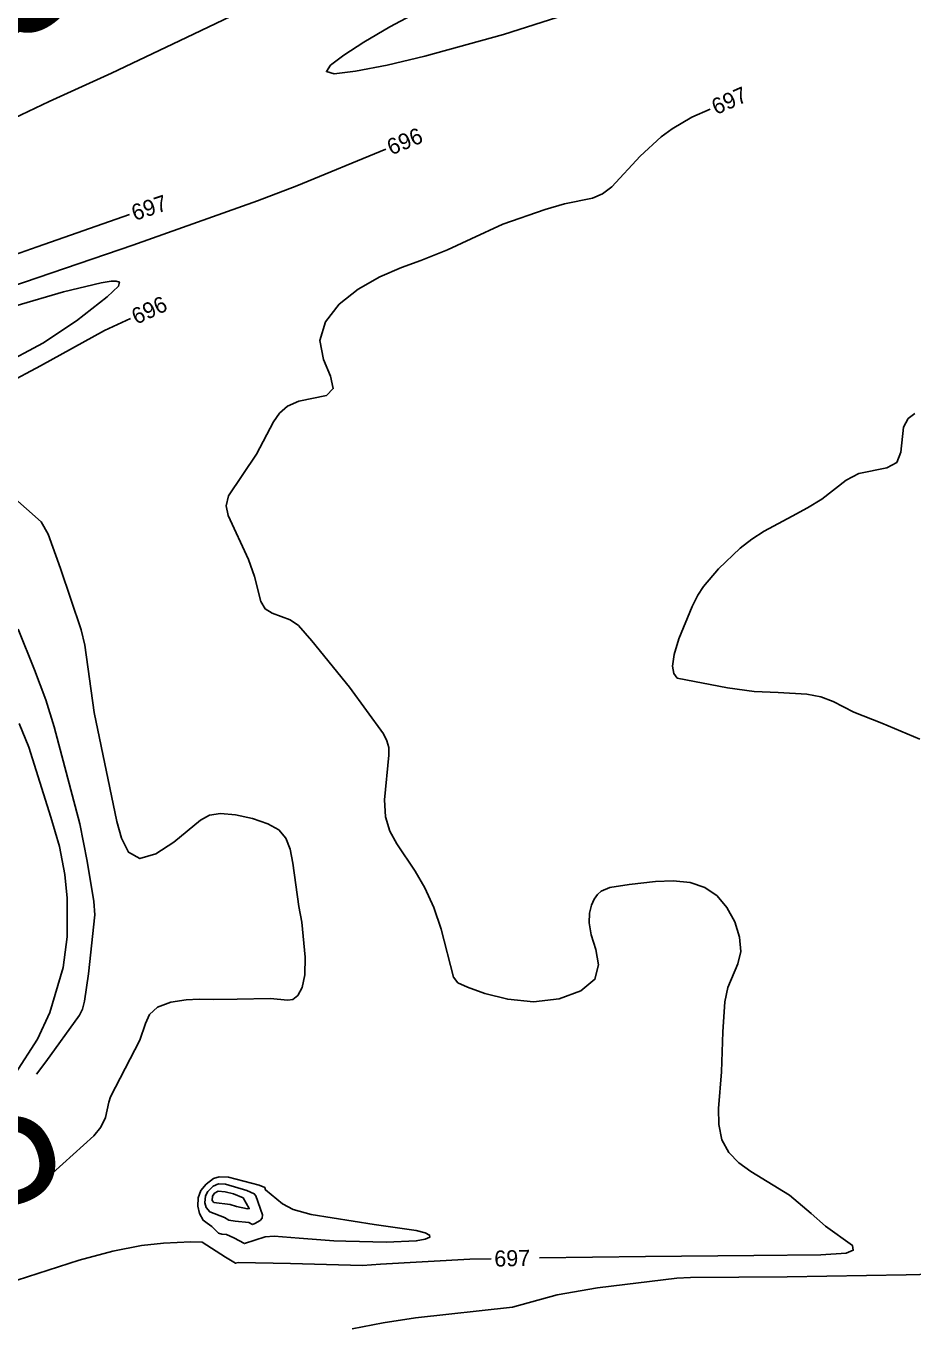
# Model space of a CAD drawing. Extents: x -291892836 to 2945206, y -477993085 to 1832792.
# Drawn here: x 1851693.8 to 1851914.3, y 543914.3 to 544238.1 of the extents above; entities that cross this region are included whole.
import ezdxf

# ---------------------------------------------------------------- set-up
doc = ezdxf.new("R2010")
doc.units = 0
for name, color, linetype in [('DT_X_Contour_Minor', 7, 'Continuous'), ('DT_X_Terrain_Ground_Line', 7, 'Continuous'), ('Level 19', 7, 'Continuous')]:
    doc.layers.add(name, color=color, linetype=linetype)

msp = doc.modelspace()

# ---------------------------------------------------------------- linework, layer by layer
at = {"layer": 'DT_X_Contour_Minor'}
for points in [[(1851931.69, 544281.76), (1851910.49, 544273.12), (1851880.59, 544261.04), (1851851.63, 544249.92), (1851827.79, 544240.92), (1851812.52, 544236.04), (1851792.96, 544230.62), (1851783.55, 544228.39), (1851775.68, 544226.85), (1851770.39, 544226.25), (1851768.46, 544226.78), (1851769.49, 544228.37), (1851772.8, 544230.86), (1851777.79, 544234.1), (1851784.27, 544237.92), (1851792.16, 544242.16), (1851820.5, 544255.9), (1851837.67, 544264.91), (1851860.88, 544277.83), (1851881.54, 544289.37), (1851910.29, 544305.1), (1851930.59, 544315.55)], [(1851761.6, 544248.69), (1851735.43, 544236.06), (1851715.03, 544226.43), (1851699.52, 544219.38), (1851687.28, 544213.58), (1851657.96, 544200.39), (1851642.9, 544193.34), (1851622.56, 544183.28), (1851599.45, 544170.67), (1851574.61, 544158.3), (1851546, 544145.08), (1851535.48, 544140.27), (1851545.35, 544141.39), (1851563.49, 544143.64), (1851572.51, 544144.56), (1851577.67, 544145.61), (1851591.83, 544149.73), (1851603.5, 544153.32), (1851607.02, 544154.06), (1851619.76, 544157.73), (1851652.44, 544167.79), (1851666.89, 544172.72), (1851696.51, 544183.18), (1851719.47, 544191.24)], [(1851701.81, 544242.92), (1851692.99, 544237.39), (1851689.94, 544235.33), (1851685.86, 544232.88), (1851672.96, 544226.1), (1851648.68, 544213.9), (1851621.28, 544200.35), (1851614.41, 544197.2), (1851607.53, 544194.36), (1851583.78, 544185.51), (1851556.7, 544174.12), (1851530.45, 544164.25), (1851502.49, 544153.19), (1851472.56, 544141.47), (1851436.91, 544127.59), (1851413.91, 544119.01), (1851376.2, 544105.75), (1851343.56, 544094.54), (1851329.79, 544091.13), (1851296.36, 544083.01), (1851285.66, 544080.19), (1851270.99, 544072.75)], [(1851863.88, 544217.47), (1851859.34, 544215.46), (1851854.46, 544212.53), (1851851.73, 544210.55), (1851846.46, 544205.74), (1851839.44, 544198.12), (1851837.12, 544196.35), (1851834.6, 544195.33), (1851827.7, 544193.86), (1851822.82, 544192.51), (1851812.36, 544188.79), (1851804.43, 544185.21), (1851798.6, 544182.45), (1851791.92, 544179.82), (1851787.15, 544178.03), (1851781.75, 544175.69), (1851776.36, 544172.67), (1851771.62, 544168.9), (1851768.22, 544164.55), (1851766.84, 544159.89), (1851767.75, 544155.2), (1851769.49, 544151.02), (1851770.18, 544147.92), (1851768.47, 544146.25), (1851761.57, 544144.76), (1851758.77, 544143.54), (1851756.76, 544141.8), (1851755.3, 544139.7), (1851751.08, 544131.62), (1851744.11, 544121.28), (1851743.51, 544118.74), (1851744.06, 544116.38), (1851749.11, 544105.38), (1851750.61, 544101.18), (1851752.18, 544094.98), (1851753.19, 544093.13), (1851754.94, 544092.06), (1851759.46, 544090.44), (1851761.48, 544088.99), (1851764.84, 544085.19), (1851774.22, 544073.62), (1851782.62, 544062.01), (1851783.52, 544060.29), (1851783.94, 544058.68), (1851783.96, 544056.75), (1851782.94, 544045.67), (1851783.18, 544041.38), (1851784.21, 544037.8), (1851785.93, 544034.67), (1851790.53, 544027.91), (1851792.97, 544023.72), (1851795.19, 544018.87), (1851797.02, 544013.44), (1851800.06, 544001.51), (1851801.18, 544000.14), (1851803.58, 543999.01), (1851807.86, 543997.49), (1851813.57, 543996.04), (1851819.99, 543995.4), (1851826.36, 543996.12), (1851831.75, 543998.09), (1851835.22, 544001.02), (1851836.15, 544004.61), (1851835.43, 544008.43), (1851834.3, 544012.02), (1851833.78, 544015.03), (1851833.87, 544017.46), (1851834.35, 544019.39), (1851835.03, 544020.92), (1851835.85, 544022.08), (1851836.78, 544022.91), (1851838.96, 544023.82), (1851843.71, 544024.58), (1851850.33, 544025.3), (1851854.68, 544025.45), (1851858.93, 544025.04), (1851862.59, 544023.81), (1851865.61, 544021.73), (1851868.06, 544018.86), (1851869.98, 544015.3), (1851871.2, 544011.47), (1851871.49, 544007.87), (1851870.78, 544004.81), (1851868.26, 543998.95), (1851867.49, 543995.36), (1851867.02, 543987.94), (1851866.73, 543977.93), (1851865.93, 543968.87), (1851866.02, 543964.88), (1851866.81, 543961.09), (1851868.52, 543957.93), (1851871, 543955.33), (1851873.98, 543953.14), (1851883.64, 543947.26), (1851888.97, 543942.77), (1851892.59, 543939.57), (1851899.26, 543934.77), (1851899.48, 543933.59), (1851897.68, 543932.89), (1851891.39, 543932.45), (1851874.73, 543932.3)], [(1851689.97, 544173.25), (1851720.33, 544183.6), (1851751.34, 544194.65), (1851761.1, 544198.39), (1851783.21, 544207.51)], [(1851687.43, 544153.59), (1851697.91, 544159.21), (1851706.3, 544164.81), (1851713.97, 544170.72), (1851716.73, 544173.43), (1851717.03, 544174.39), (1851716.19, 544174.67), (1851714.97, 544174.64), (1851712.49, 544174.25), (1851703.06, 544171.99), (1851691.27, 544168.51)], [(1851719.77, 544165.33), (1851713.3, 544162.35), (1851697.37, 544153.57), (1851689.03, 544149.1)], [(1851916.04, 544060.73), (1851906.57, 544064.7), (1851899.58, 544067.42), (1851894.51, 544070.09), (1851891.4, 544071.24), (1851887.89, 544071.91), (1851880.78, 544072.32), (1851874.84, 544072.6), (1851868.19, 544073.52), (1851855.68, 544075.92), (1851854.83, 544077.04), (1851854.51, 544078.92), (1851854.91, 544081.78), (1851856.1, 544085.66), (1851859.42, 544093.75), (1851860.84, 544096.55), (1851862.2, 544098.68), (1851865.98, 544103.1), (1851871.34, 544108.21), (1851874.22, 544110.44), (1851877.28, 544112.44), (1851884.31, 544116.23), (1851888.09, 544118.24), (1851891.64, 544120.45), (1851897.72, 544125.13), (1851900.88, 544126.79), (1851907.83, 544128.22), (1851910.28, 544129.52), (1851911.33, 544132.09), (1851911.95, 544138.34), (1851913.09, 544140.45), (1851914.75, 544141.71)], [(1851690.21, 544121.26), (1851697.54, 544114.76), (1851699.27, 544111.72), (1851702.31, 544103.21), (1851707.5, 544087.95), (1851708.39, 544084.12), (1851710.72, 544067.34), (1851716.38, 544040.26), (1851717.49, 544036.11), (1851719.28, 544032.6), (1851722.09, 544031.01), (1851726.08, 544032.16), (1851730.51, 544035.06), (1851737.18, 544040.54), (1851739.42, 544041.8), (1851742.09, 544042.19), (1851745.84, 544041.86), (1851750.08, 544040.97), (1851753.92, 544039.69), (1851756.65, 544038.14), (1851758.4, 544036.13), (1851759.47, 544033.4), (1851760.15, 544029.86), (1851761.59, 544019.11), (1851762.35, 544015.21), (1851763.19, 544006.46), (1851763.12, 544002.1), (1851762.46, 543998.94), (1851761.38, 543996.97), (1851760.14, 543995.99), (1851758.85, 543995.77), (1851754.45, 543996.18), (1851746.26, 543996.03), (1851740.44, 543995.94), (1851736.84, 543996.06), (1851733.58, 543995.86), (1851729.77, 543995.26), (1851726.49, 543994.07), (1851724.49, 543992.2), (1851723.47, 543989.96), (1851722.07, 543985.85), (1851714.76, 543971.79), (1851714.35, 543970.43), (1851713.53, 543966.64), (1851712.4, 543964.17), (1851710.66, 543962.06), (1851700.31, 543952.73), (1851695.62, 543948.99), (1851687.7, 543943.83)], [(1851696.41, 543977.38), (1851698.72, 543980.46), (1851707.08, 543992.07), (1851707.77, 543993.59), (1851708.32, 543995.57), (1851709.34, 544002.36), (1851710.86, 544017.06), (1851710.65, 544020.31), (1851708.95, 544030.39), (1851707.11, 544039.65), (1851700.73, 544063.83), (1851698.73, 544070.53), (1851695.89, 544077.95), (1851691.85, 544088.06)], [(1851696.64, 543986.06), (1851699.72, 543992.7), (1851702.97, 544003.89), (1851703.98, 544011.56), (1851703.99, 544021.2), (1851703.42, 544027.05), (1851702.07, 544034.04), (1851699.93, 544041.34), (1851694.48, 544058.73), (1851692.08, 544064.63)], [(1851691.06, 543977.47), (1851696.64, 543986.06)], [(1851773.29, 543935.82), (1851783.41, 543935.57), (1851790.8, 543935.89), (1851793.03, 543936.31), (1851794.16, 543936.82), (1851794.13, 543937.38), (1851792.99, 543937.95), (1851790.81, 543938.5), (1851780.37, 543940.03), (1851764.64, 543942.5), (1851760.22, 543943.74), (1851757.56, 543945.15), (1851753.35, 543948.61), (1851753.11, 543949.2), (1851751.74, 543949.74), (1851744.14, 543951.78), (1851741.78, 543951.85), (1851740.37, 543951.4), (1851738.53, 543950.02), (1851737.24, 543948.42), (1851736.59, 543946.59), (1851736.48, 543944.55), (1851736.94, 543942.75), (1851737.8, 543941.06), (1851738.8, 543940.35), (1851739.97, 543939.46), (1851741.62, 543937.85), (1851742.49, 543937.62), (1851743.63, 543937.48), (1851745.47, 543936.7), (1851748.07, 543935.23), (1851753.23, 543936.92), (1851755.44, 543937.06), (1851761.68, 543936.6), (1851770.33, 543935.92), (1851773.29, 543935.82)], [(1851750.1, 543940.03), (1851750.63, 543940.25), (1851752.01, 543940.99), (1851752.51, 543941.6), (1851752.56, 543942.36), (1851750.93, 543947.1), (1851750.5, 543947.6), (1851748.7, 543948.45), (1851743.37, 543950), (1851741.65, 543950.07), (1851740.34, 543949.54), (1851738.95, 543948.21), (1851738.43, 543947.12), (1851738.25, 543945.39), (1851738.56, 543944.24), (1851739.47, 543943.15), (1851743.11, 543941.73), (1851744.23, 543941.07), (1851745.79, 543940.8), (1851749.17, 543940.5), (1851750.1, 543940.03)], [(1851747.8, 543946.65), (1851749.27, 543943.94), (1851748.86, 543943.89), (1851746.11, 543944.48), (1851744.53, 543944.93), (1851740.49, 543945.46), (1851740.07, 543946), (1851740.1, 543947), (1851740.6, 543947.78), (1851741.52, 543948.3), (1851743.27, 543948.13), (1851745.37, 543947.6), (1851747.8, 543946.65)], [(1851809.46, 543931.48), (1851804.12, 543931.36), (1851781.95, 543930.14), (1851777.41, 543929.79), (1851759.53, 543930.31), (1851746.52, 543930.58), (1851745.86, 543930.36), (1851743.39, 543931.87), (1851737.59, 543935.56), (1851734.78, 543935.71), (1851727.96, 543935.38), (1851722.44, 543934.74), (1851715.39, 543933.39), (1851706.99, 543931.16), (1851691.55, 543926.17), (1851679.67, 543922.05), (1851658.85, 543916.77), (1851639.06, 543912.21)], [(1851874.73, 543932.3), (1851847.81, 543932.02), (1851821.46, 543931.74)], [(1851774.86, 543914.03), (1851782.59, 543915.55), (1851790.58, 543916.74), (1851814.72, 543919.46), (1851825.83, 543922.49), (1851835.87, 543924.23), (1851855.59, 543926.67), (1851859, 543926.81), (1851883.01, 543927.01), (1851912.66, 543927.48), (1851936.26, 543928.02)]]:
    msp.add_lwpolyline(points, dxfattribs=at)

# ---------------------------------------------------------------- texts
at = {"layer": 'DT_X_Terrain_Ground_Line'}
for rotation, p in [(36.3484, (1851651.31, 544203.09)), (22.0474, (1851637.46, 543923.29))]:
    msp.add_text('695', height=33, rotation=rotation, dxfattribs=at).set_placement(p)
at = {"layer": 'Level 19'}
for s, rotation, p in [('697', 23.858, (1851865.37, 544215.94)), ('696', 22.4141, (1851784.57, 544205.91)), ('697', 18.4893, (1851720.8, 544189.61)), ('696', 24.7747, (1851721.19, 544163.78)), ('697', 1.3178, (1851810.25, 543929.5))]:
    msp.add_text(s, height=4, rotation=rotation, dxfattribs=at).set_placement(p)

doc.saveas('drawing.dxf')
